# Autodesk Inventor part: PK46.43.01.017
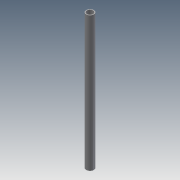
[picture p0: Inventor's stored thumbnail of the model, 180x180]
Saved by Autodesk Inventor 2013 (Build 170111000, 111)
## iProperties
Shininess: 64.0
Length Units: 11269
Angle Units: 11279
Time Units: 11290
Mass Units: 11283
Length Display Precision: 3
Angle Display Precision: 2
Compacted: True
Part Number: PK46.43.01.017
Document SubType Name: Modeling
Created: 2004-12
Material: Steel, Mild
Designer: ELarisa
Manufacturer: Standard
Standards Organization: Custom
Density: 7.86 g/cm^3
Mass: 611.15 g
Surface Area: 625.57 cm^2
Volume: 77.7544 cm^3
Density: 0.0
Volumn: 0.0
Area: 0.0
PropertySet Name: Model Information
Control State: 0
Master: False
Checked Out: False
Checked Out Date: 2008-10-09
Last Check In Date: 2008-10-09
Author: ELarisa
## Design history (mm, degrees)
sketch "Эскиз1"
  geometry: C1 r 10 at (-7.57, 2.54); C2 r 12.5 at (-7.57, 2.54)
  constraints: 2 centre point, 1 coincident
  dimensions: "d0" = 25 diameter of C2; "d1" = 20 diameter of C1
extrude "Выдавливание2" new body sketch "Эскиз1" distance "d10" = 440; taper "d11" = 0 deg
body "Solid1"
